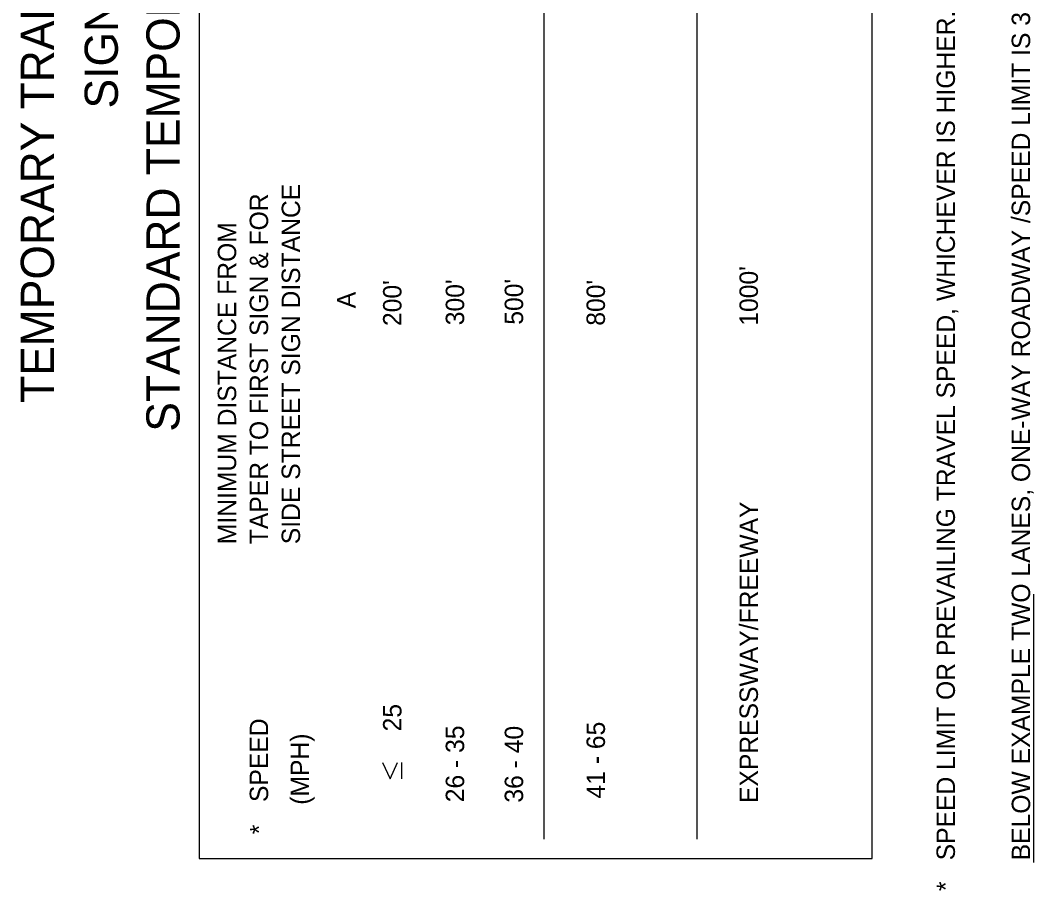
# Model space of a CAD drawing. Extents: x 610.92 to 617.75, y 610.91 to 620.34.
# Drawn here: x 610.921 to 614.226, y 613.215 to 616.047 of the extents above; entities that cross this region are included whole.
import ezdxf

# ---------------------------------------------------------------- set-up
doc = ezdxf.new("R2010")
doc.units = 0
doc.layers.add('DETL-NOTE', color=7, linetype='Continuous')
doc.layers.add('DETL-TITL', color=7, linetype='Continuous')

msp = doc.modelspace()

# ---------------------------------------------------------------- linework, layer by layer
at = {"layer": 'DETL-NOTE'}
for p, q in [((611.503, 620.3372), (611.503, 613.3204)), ((613.6939, 613.3204), (613.6939, 620.3372)), ((612.6246, 620.1996), (612.6246, 613.3828)), ((613.1225, 620.1996), (613.1225, 613.3828)), ((614.2192, 613.3071), (614.2192, 614.1797)), ((612.0998, 613.6324), (612.1249, 613.579)), ((612.1249, 613.579), (612.1484, 613.6324)), ((612.1613, 613.6324), (612.1613, 613.579)), ((611.503, 613.3204), (613.6939, 613.3204))]:
    msp.add_line(p, q, dxfattribs=at)

# ---------------------------------------------------------------- texts
for s, p in [('BELOW EXAMPLE TWO LANES, ONE-WAY ROADWAY /SPEED LIMIT IS 35 MPH /PREVAILING SPEED IS 38 MPH (USE 40 MPH)', (614.2077, 613.314)), ('SPEED LIMIT OR PREVAILING TRAVEL SPEED, WHICHEVER IS HIGHER.', (613.9629, 613.314)), ('SIDE STREET SIGN DISTANCE', (611.8312, 614.3424)), ('TAPER TO FIRST SIGN & FOR', (611.7272, 614.3424)), ('MINIMUM DISTANCE FROM', (611.6232, 614.3424)), ("1000'", (613.3216, 615.0532)), ("200'", (612.1613, 615.0521)), ("300'", (612.3653, 615.0547)), ("500'", (612.5573, 615.0564)), ("800'", (612.8237, 615.0532)), ('A', (612.0117, 615.1099)), ('EXPRESSWAY/FREEWAY', (613.3217, 613.5004)), ('25', (612.1613, 613.7334)), ('SPEED', (611.7273, 613.5036)), ('41 - 65', (612.8237, 613.5151)), ('26 - 35', (612.3653, 613.5029)), ('36 - 40', (612.5573, 613.5017)), ('(MPH)', (611.8605, 613.4948)), ('*', (611.7277, 613.3988)), ('*', (613.9629, 613.214))]:
    msp.add_text(s, height=0.06, rotation=90, dxfattribs=at).set_placement(p)
at = {"layer": 'DETL-TITL'}
for s, p in [('STANDARD TEMPORARY TRAFFIC CONTROL OPERATIONS', (611.4389, 614.7084)), ('TEMPORARY TRAFFIC CONTROL TYPICAL APPLICATION', (611.0301, 614.802)), ('SIGN SPACING CHART', (611.2381, 615.7599))]:
    msp.add_text(s, height=0.108, rotation=90, dxfattribs=at).set_placement(p)

doc.saveas('drawing.dxf')
